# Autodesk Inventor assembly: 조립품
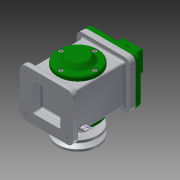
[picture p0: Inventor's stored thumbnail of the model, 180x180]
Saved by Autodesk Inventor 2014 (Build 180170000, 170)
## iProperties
Created: 2017-08
Part Number: 조립품
Document SubType Name: Assembly
Designer: user
Author: user
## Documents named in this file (18)
- C:\Users\user\Desktop\470808V1011\조립품.iam
- C:\Users\user\Desktop\470808V1011\본체.ipt
- C:\Users\user\Desktop\470808V1011\V-벨트풀리.ipt
- C:\Users\user\Desktop\470808V1011\편심축.ipt
- C:\Users\user\Desktop\470808V1011\키 4 x 4 x 12.ipt
- C:\Users\user\Desktop\470808V1011\와셔 4x16.ipt
- C:\Users\user\Desktop\470808V1011\볼트 M4 x 10.ipt
- C:\Users\user\Desktop\470808V1011\베어링 17 x 40 x 12.ipt
- C:\Users\user\Desktop\470808V1011\뒤커버.ipt
- C:\Users\user\Desktop\470808V1011\덮개.ipt
- C:\Users\user\Desktop\470808V1011\앞커버.ipt
- C:\Users\user\Desktop\470808V1011\오일 실 17 30 8.ipt
- C:\Users\user\Desktop\470808V1011\링크.ipt
- C:\Users\user\Desktop\470808V1011\슬라이더.ipt
- C:\Users\user\Desktop\470808V1011\클레비스 핀 6 x 22.ipt
- 클레비스 핀 6 x 22.ipt
- C:\Users\user\Desktop\470808V1011\E-링.ipt
- C:\Users\user\Desktop\470808V1011\볼트 M4 x 8.ipt
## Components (2 placed, 2 different names)
1. V-벨트풀리:1 — 각도:2
2. E-링:1
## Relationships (1: Angle 1)
- 각도:2 [Angle]: V-벨트풀리:1
